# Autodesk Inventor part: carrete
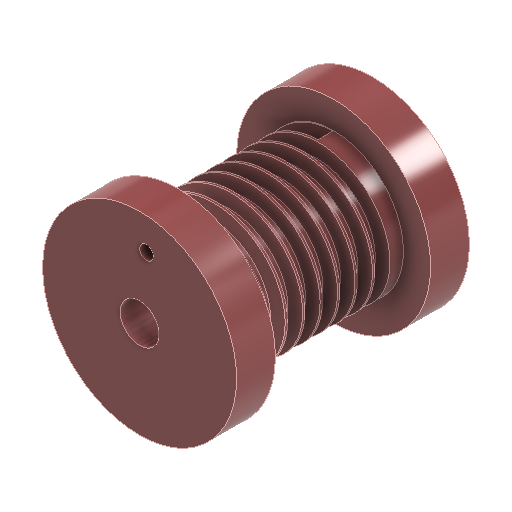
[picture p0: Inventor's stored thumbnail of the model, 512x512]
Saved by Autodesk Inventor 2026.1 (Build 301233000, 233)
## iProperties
Created: 2025-06
Part Number: carrete
Material: Genérico
Document SubType Name: Modeling
Designer: piero
Density: 1 g/cm^3
Appearance: Castaño
Author: piero
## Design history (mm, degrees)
sketch "Boceto1"
  geometry: C1 r 25 at (0, 0); C2 r 4 at (0, 0); C3 r 11 at (0, 0); 1 further point
  constraints: 3 centre point, 3 coincident
  dimensions: "d0" = 50 diameter of C1; "d3" = 8 diameter of C2; "d34" = 22 diameter of C3
extrude "Extrusión1" new body sketch "Boceto1" distance "d1" = 10; taper "d2" = 0 deg
sketch "Boceto5"
  geometry: C1 r 5 at (0, 0); C2 r 18 at (0, 0); 1 further point
  constraints: 2 centre point, 2 coincident
  dimensions: "d15" = 10 diameter of C1; "d16" = 36 diameter of C2
extrude "Extrusión5" join sketch "Boceto5" distance "d17" = 40; taper "d18" = 0 deg
sketch "Boceto6"
  geometry: C1 r 4 at (0, 0) reference; C2 r 25 at (0, 0); C3 r 4 at (0, 0); C4 r 5 at (0, 0) reference; C5 r 11 at (0, 0); 1 further point
  constraints: 3 centre point, 2 coincident
  dimensions: "d22" = 50 diameter of C2; "d30" = 8 diameter of C3; "d31" = 22 diameter of C5
extrude "Extrusión6" join sketch "Boceto6" distance "d23" = 10; taper "d24" = 0 deg
sketch "Boceto18"
  geometry: L1 (18, 10)-(18, 50) reference; L2 (18, 50)-(18, 46.125); L3 (18, 50)-(18, 46.125); L4 (18, 46.125)-(15, 46.901); L5 (15, 46.901)-(15, 49.224); L6 (15, 49.224)-(18, 50); C1 r 1.5 at (16.5, 48.063); 6 further points; 1 other entity
  constraints: 11 end point, 3 tangent, 1 centre point, 1 collinear, 1 equal length, 2 other
  dimensions: "d109" = 3 distance between parallel lines of L1 L5; "d110" = 3 diameter of C1; "d127" = 29 deg angle of L6 L4
feature "Bobina1" sketch "Boceto18" pitch "d99" = 4.5; turns "d101" = 8; dims "d100" = 35, "d102" = 0, angle "d103" = 90 deg, angle "d104" = 90 deg, "d105" = 0, "d106" = 0
sketch "Boceto19"
  geometry: L1 (0, 15)-(0, 18) reference; L2 (0, 18)-(0, 0); C1 r 1.75 at (1.75, 16.658); C2 r 5 at (0, 0) reference; C3 r 15 at (0, 0); 1 further point
  constraints: 2 centre point, 2 end point, 2 tangent, 1 coincident, 1 vertical
  dimensions: "d111" = 3.5 diameter of C1; "d114" = 30 diameter of C3
extrude "Extrusión13" cut sketch "Boceto19" distance "d112" = 13; taper "d113" = 0 deg
sketch "Boceto20"
  geometry: L1 (0, 15)-(0, 18); C1 r 1.75 at (-1.75, 16.658) reference; A1 r 15 centre (0, 0) between (0, 15) and (-1.567, 14.918); A2 r 18 centre (0, 0) between (0, 18) and (-0.614, 17.99); A3 r 1.75 centre (-1.75, 16.658) between (-1.567, 14.918) and (-0.614, 17.99); 4 further points
  constraints: 6 point on circle, 3 centre point, 3 coincident, 2 end point, 1 vertical
extrude "Extrusión14" join sketch "Boceto20" distance "d117" = 4.2; taper "d118" = 0 deg
node "Sólido1"
